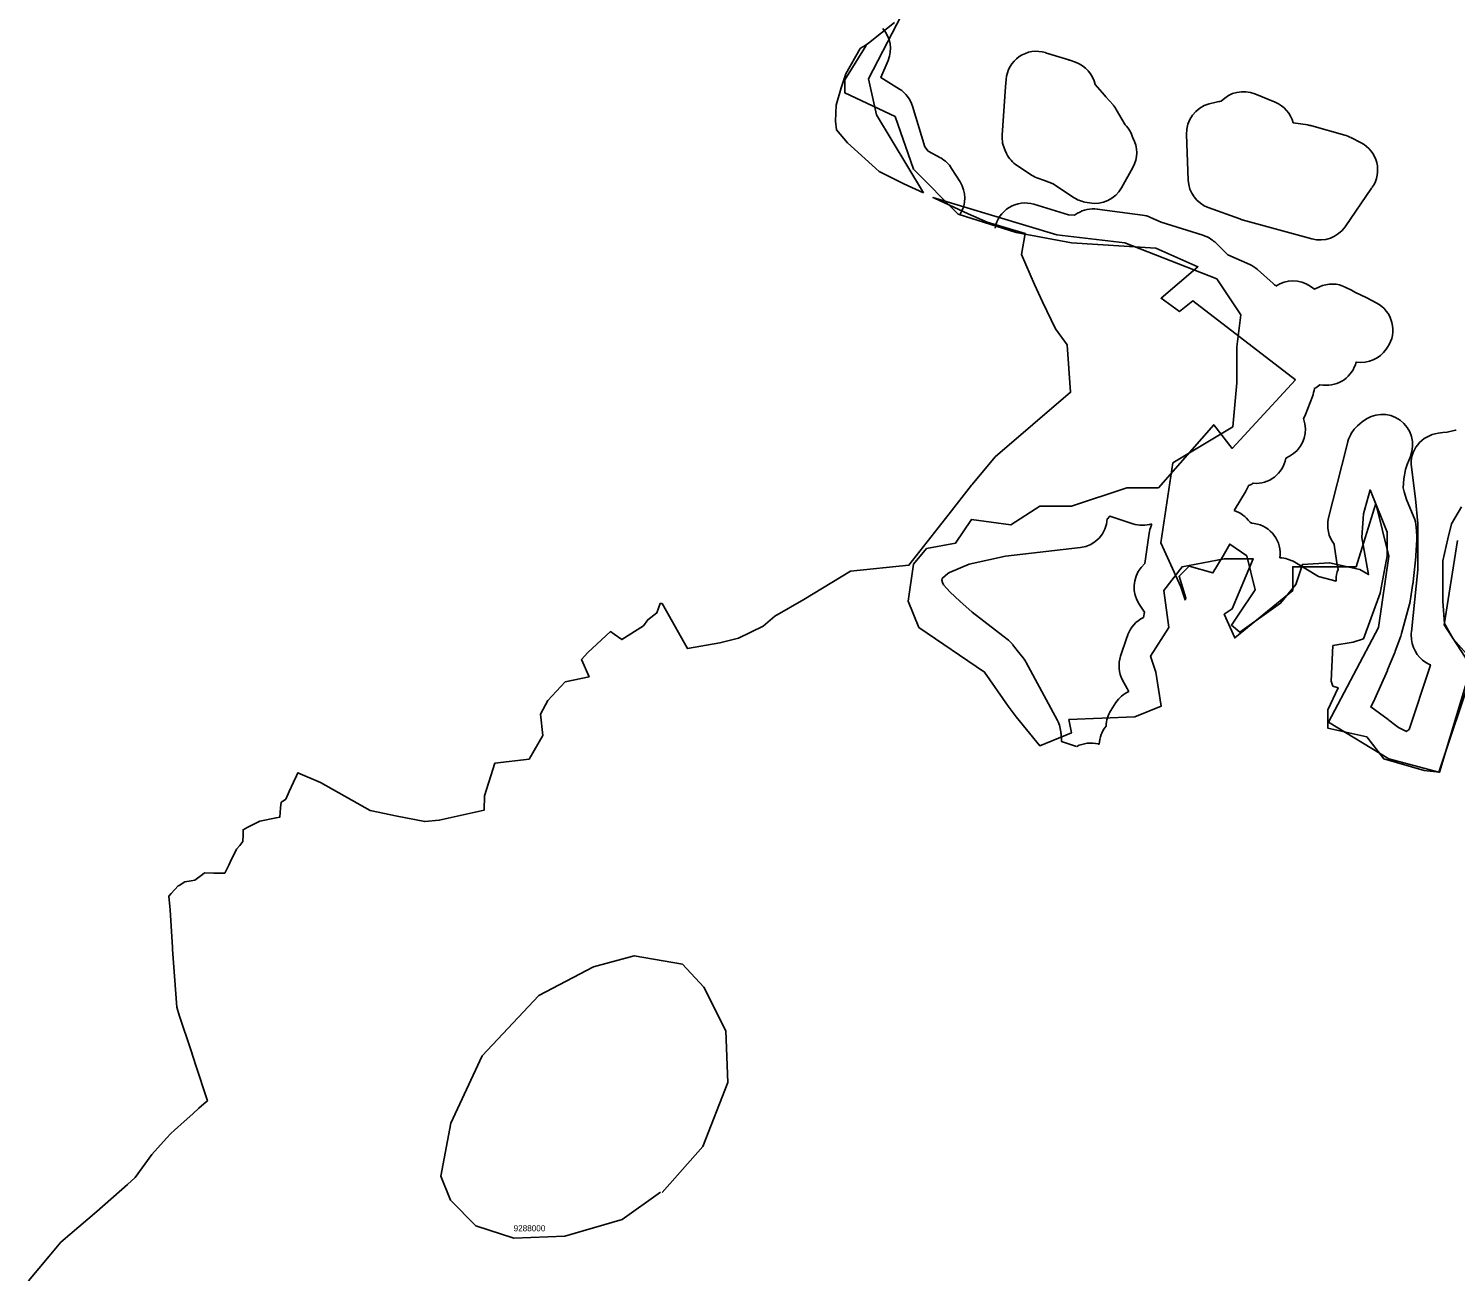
# Model space of a CAD drawing. Extents: x -546762 to -536351, y -1046851 to -1035695.
# Drawn here: x -546557 to -544214, y -1044099 to -1042054 of the extents above; entities that cross this region are included whole.
import ezdxf

# ---------------------------------------------------------------- set-up
doc = ezdxf.new("R2010")
doc.units = 0
for name, color, linetype in [('Vrstva 23', 7, 'Continuous'), ('Vrstva 24', 7, 'Continuous'), ('Vrstva 25', 7, 'Continuous'), ('Vrstva 43', 7, 'Continuous')]:
    doc.layers.add(name, color=color, linetype=linetype)

msp = doc.modelspace()

# ---------------------------------------------------------------- linework, layer by layer
at = {"layer": 'Vrstva 23'}
for points in [[(-544849.2, -1042105.3), (-544887.3, -1042093.6)], [(-544837.8, -1042109.3), (-544847.3, -1042106)], [(-545127.1, -1042153.4), (-545157.4, -1042134.6), (-545145.6, -1042106.3)], [(-544952.8, -1042149.8), (-544958.4, -1042229.1)], [(-544951.9, -1042137.8), (-544952.8, -1042149.7)], [(-544788, -1042166.1), (-544790.3, -1042163.5), (-544805.6, -1042145.9)], [(-544776.4, -1042179.4), (-544788, -1042166.1)], [(-544606.9, -1042174.8), (-544618.3, -1042177.7)], [(-544510.2, -1042175.1), (-544543.6, -1042161.4)], [(-545059.4, -1042266.5), (-545079.7, -1042255.2), (-545085.6, -1042248.3), (-545105.6, -1042181.6)], [(-544756.2, -1042212.2), (-544771, -1042186.9)], [(-544456.6, -1042212.4), (-544480.6, -1042208.9)], [(-544395.8, -1042229), (-544450.2, -1042213.7)], [(-544655.8, -1042228.1), (-544652.9, -1042303)], [(-544368.8, -1042241.8), (-544386.2, -1042232.8)], [(-544953.4, -1042254.5), (-544951.1, -1042259.3)], [(-545027.3, -1042305.9), (-545041.4, -1042283.6)], [(-544933.8, -1042279.1), (-544911.7, -1042293.7)], [(-544762.3, -1042315.5), (-544743.7, -1042282.3)], [(-544901.4, -1042299), (-544888.8, -1042303.6), (-544874.9, -1042308.8), (-544841.2, -1042331.3)], [(-544395.4, -1042379.6), (-544351.9, -1042316.4)], [(-544351.9, -1042316.3), (-544350.6, -1042314.5)], [(-544822.5, -1042339), (-544815.1, -1042340.3)], [(-544834.9, -1042357.4), (-544839.6, -1042360.3), (-544849.6, -1042359.9), (-544906.2, -1042342.7)], [(-544728.2, -1042360.5), (-544802.2, -1042350.5)], [(-544619.9, -1042348.1), (-544568.1, -1042366.8)], [(-544628.7, -1042393.5), (-544697.2, -1042371.8), (-544715, -1042364.1)], [(-544564.4, -1042368), (-544449.9, -1042399.5)], [(-544613.2, -1042401.6), (-544615.6, -1042399.9)], [(-544552, -1042441.6), (-544587.9, -1042425.7), (-544606, -1042407.5)], [(-544513.4, -1042472.8), (-544539.1, -1042449.9)], [(-544437.5, -1042478.2), (-544445.5, -1042481.9), (-544452.7, -1042476.9)], [(-544379.2, -1042486.8), (-544384.8, -1042483.9), (-544394, -1042479.2)], [(-544344.1, -1042504.7), (-544359.9, -1042496.6), (-544379.1, -1042486.8)], [(-544327.8, -1042580.6), (-544325.6, -1042577.5)], [(-544377.2, -1042601.7), (-544376.4, -1042601.8)], [(-544436.6, -1042639), (-544431.4, -1042639.6)], [(-544460.4, -1042688), (-544449, -1042658.5)], [(-544461.5, -1042703.4), (-544462.4, -1042698.9)], [(-544367.1, -1042700), (-544374.9, -1042706.8)], [(-544214.1, -1042713.9), (-544228, -1042717), (-544234.7, -1042717.8), (-544242.8, -1042718.8)], [(-544390.7, -1042732.4), (-544393.5, -1042743.7), (-544422.4, -1042858)], [(-544492.7, -1042759.9), (-544486.7, -1042756.6)], [(-544282.5, -1042856.7), (-544294.7, -1042827.7), (-544298.6, -1042815.2), (-544300, -1042808.6), (-544298.9, -1042793.6), (-544296.4, -1042778.3), (-544293.7, -1042770.2), (-544288.2, -1042757)], [(-544286.4, -1042774.6), (-544280, -1042826.3), (-544276, -1042866.9), (-544275.9, -1042942.9), (-544286.5, -1043044.8)], [(-544554.6, -1042806.2), (-544554.5, -1042805.7)], [(-544553.7, -1042804.8), (-544550.7, -1042803.3)], [(-544577.4, -1042845.8), (-544566.4, -1042827.6), (-544558.9, -1042815.1)], [(-544785.7, -1042859.3), (-544781.8, -1042855), (-544743.7, -1042867.5)], [(-544712.7, -1042867.6), (-544713, -1042868.5)], [(-544544.4, -1042866.9), (-544548.4, -1042866.3), (-544551.9, -1042864.6)], [(-544277.6, -1042887.7), (-544278.7, -1042872.7)], [(-544717, -1042882.9), (-544724.2, -1042932.6)], [(-544413.3, -1042901), (-544412.6, -1042905.9), (-544408.5, -1042935)], [(-544279, -1042919.4), (-544277.6, -1042893.9)], [(-544950.2, -1043057), (-545007.8, -1043012.5), (-545027.9, -1042994.5), (-545027.9, -1042994.5), (-545043.9, -1042980), (-545054.8, -1042967.6), (-545056.3, -1042964.1), (-545057.2, -1042959.9), (-545056.9, -1042957.6), (-545056.4, -1042956.6), (-545047.7, -1042949.3), (-545044.7, -1042947.6), (-545012.6, -1042933.8), (-544952.8, -1042920.9), (-544829.9, -1042906.5)], [(-544283.7, -1042963.1), (-544279.2, -1042922)], [(-544724.3, -1042932.7), (-544730, -1042939.5)], [(-544410.1, -1042959.8), (-544410.1, -1042961.6), (-544439.1, -1042954.1), (-544478.1, -1042930.7)], [(-544407.5, -1042939.8), (-544406.9, -1042942.4)], [(-544288.5, -1042994.4), (-544284, -1042965.6)], [(-544733.5, -1042999.8), (-544724.7, -1043012.9), (-544726.3, -1043021.5)], [(-544302.7, -1043048), (-544289.6, -1042999.6)], [(-544935.2, -1043073.6), (-544941.6, -1043065.6)], [(-544752.3, -1043050.7), (-544753.5, -1043054.1), (-544763.9, -1043084.9)], [(-544313, -1043077), (-544304, -1043052.1)], [(-544286.6, -1043054.7), (-544286.3, -1043057.6)], [(-544923.8, -1043088), (-544933.7, -1043075.5), (-544935.2, -1043073.7)], [(-544325.5, -1043107.4), (-544313.8, -1043079)], [(-544867.7, -1043190.5), (-544919, -1043095.3)], [(-544346.5, -1043155.2), (-544326, -1043108.5)], [(-544256.7, -1043098.6), (-544255.2, -1043099.2), (-544256.9, -1043104.5), (-544290, -1043205.4)], [(-544760.6, -1043124.4), (-544753.3, -1043138.1)], [(-544324.7, -1043188.9), (-544353.1, -1043168.3), (-544347.8, -1043157.8)], [(-544771.5, -1043161.2), (-544779.8, -1043174.1)], [(-544311.9, -1043198.8), (-544323.3, -1043189.9)], [(-544294.8, -1043208.5), (-544307.5, -1043202.3), (-544311.9, -1043198.9)], [(-544836.1, -1043233.3), (-544861.2, -1043225.1), (-544861.8, -1043212)], [(-544799.1, -1043229.7), (-544800.7, -1043229.3)]]:
    msp.add_lwpolyline(points, dxfattribs=at)
for centre, start, end in [((-545191.8, -1042087), 337.3847, 41.2924), ((-544902, -1042141.3), 72.8296, 175.9314), ((-544864, -1042153.1), 70.5568, 72.8296), ((-544854.5, -1042156.5), 12.1909, 70.5568), ((-544902.9, -1042153.3), 175.9314, 175.9544), ((-545153.5, -1042195.9), 16.6863, 58.1684), ((-544825.8, -1042198.9), 41.0272, 41.0307), ((-544594.3, -1042223.2), 95.0827, 104.4945), ((-544562.4, -1042207.7), 67.8064, 136.6015), ((-544529, -1042221.3), 14.3739, 67.8064), ((-544814.2, -1042212.2), 30.3979, 41.0272), ((-544605.8, -1042226.1), 104.4945, 182.2014), ((-544791.8, -1042247.4), 16.13, 44.6377), ((-544463.7, -1042261.9), 74.3371, 81.817), ((-544908.5, -1042232.6), 175.9544, 205.9892), ((-544787.4, -1042257.9), 330.8125, 29.2104), ((-544409.3, -1042277.2), 62.5847, 74.3371), ((-544391.9, -1042286.2), 325.5309, 62.5847), ((-545083.7, -1042310.2), 32.1113, 60.8519), ((-544906.2, -1042237.4), 205.9892, 236.4478), ((-545069.7, -1042332.5), 328.4125, 32.1113), ((-544884.1, -1042252.1), 236.4478, 249.754), ((-544806, -1042291.2), 259.5113, 330.8125), ((-544602.9, -1042301), 182.2014, 250.1209), ((-544393.1, -1042288), 325.4753, 325.5309), ((-544813.4, -1042289.8), 236.1491, 259.5113), ((-544920.8, -1042390.5), 73.0372, 169.9655), ((-544808.8, -1042400.1), 82.3181, 121.4759), ((-544734.8, -1042410), 66.6368, 82.3181), ((-544551.1, -1042319.8), 250.1209, 254.6353), ((-544436.6, -1042351.2), 254.6353, 325.4753), ((-544643.8, -1042441.2), 55.6619, 72.4253), ((-544641.4, -1042442.9), 45, 55.6619), ((-544572.3, -1042487.3), 48.3485, 66.0771), ((-544546.6, -1042510.1), 41.6595, 48.3485), ((-544481, -1042518.2), 55.5487, 124.3809), ((-544416.8, -1042523.7), 62.8883, 114.5216), ((-544401.9, -1042531.3), 62.8902, 62.9511), ((-544366.9, -1042549.2), 325.5932, 62.8998), ((-544369, -1042552.3), 261.5678, 325.5932), ((-544425.8, -1042589.9), 263.5051, 346.4252), ((-544469.3, -1042601.2), 297.9425, 310.8958), ((-544495.6, -1042640.4), 338.8208, 354.2598), ((-544507.1, -1042669.9), 330.7642, 338.8208), ((-544334.4, -1042737.8), 337.5285, 130.8724), ((-544510.6, -1042712.7), 298.6405, 10.6575), ((-544511.5, -1042708.1), 10.6575, 16.0094), ((-544342.2, -1042744.6), 130.8724, 165.8569), ((-544190.6, -1042758), 116.62, 118.0582), ((-544236.8, -1042768.5), 96.8986, 187.0374), ((-544542, -1042751.1), 265.1649, 349.9198), ((-544601.7, -1042789.3), 328.9352, 340.2532), ((-544593.7, -1042774.7), 321.6944, 323.0556), ((-544571.8, -1042758), 295.057, 300.858), ((-544592.7, -1042893.4), 35.2337, 72.1535), ((-544835.7, -1042856.8), 276.6671, 357.2254), ((-544728.1, -1042820), 251.795, 287.8676), ((-544667.5, -1042890.2), 157.5718, 171.668), ((-544665.1, -1042882.8), 163.3626, 166.4481), ((-544551.9, -1042916.3), 351.7201, 81.3696), ((-544373.9, -1042870.2), 165.8317, 218.055), ((-544328.6, -1042876.1), 3.9255, 22.8493), ((-544327.5, -1042891.1), 356.8351, 3.9255), ((-544503.8, -1042973.5), 58.956, 88.3625), ((-544328.9, -1042916.6), 353.8265, 356.8351), ((-544692, -1042971.9), 139.5152, 213.8546), ((-544674.8, -1042939.8), 171.668, 171.8853), ((-544360.1, -1042960.1), 159.3153, 179.7451), ((-544358.9, -1042928), 188.0694, 193.6986), ((-544333.4, -1042957.8), 351.0315, 353.8265), ((-544337.9, -1042986.6), 344.9633, 351.0315), ((-544705, -1043066.7), 115.2522, 161.3619), ((-544980.8, -1043096.6), 38.3985, 52.3), ((-544350.9, -1043035), 339.9929, 344.9633), ((-544236.8, -1043050), 174.0675, 185.4499), ((-544236.5, -1043052.8), 185.4499, 246.1491), ((-544974.4, -1043104.7), 38.329, 38.3985), ((-544963, -1043119), 28.3051, 38.4181), ((-544716.5, -1043100.9), 161.359, 208.0161), ((-544360, -1043059.9), 337.5854, 339.9929), ((-544371.7, -1043088.3), 336.2394, 337.5854), ((-544729.5, -1043188.4), 114.6868, 147.139), ((-544709.2, -1043114.6), 208.0161, 214.5271), ((-544392.3, -1043135), 332.8265, 336.2394), ((-544737.8, -1043201.3), 147.139, 178.418), ((-544911.8, -1043214.2), 2.5506, 28.3051), ((-544749.1, -1043231.6), 140.6981, 177.8378), ((-544354, -1043229.4), 52.1666, 54.0551), ((-544342.6, -1043238.3), 52.125, 52.1666), ((-544265.8, -1043249.2), 119.0206, 125.5078), ((-544813, -1043277.7), 75.6926, 117.4409)]:
    msp.add_arc(centre, 50, start, end, dxfattribs=at)
at = {"layer": 'Vrstva 24'}
for points in [[(-545087.6, -1042324.1), (-545164.5, -1042195.8), (-545177.7, -1042136.7), (-545046, -1041881.4)], [(-545135.4, -1042044.2), (-545178, -1042078.1), (-545185.2, -1042082.8), (-545188, -1042084.6), (-545191.8, -1042087), (-545215.3, -1042128.1), (-545222.9, -1042151.6), (-545231, -1042179.8), (-545232.1, -1042206), (-545230.4, -1042220.5), (-545212.6, -1042241.9), (-545160.2, -1042288.8), (-545119.6, -1042309), (-545087.6, -1042324.1)], [(-544187.6, -1043100.8), (-544240.4, -1043275.7), (-544265.3, -1043273), (-544332, -1043253.5), (-544359.8, -1043217.4), (-544423.6, -1043203.5), (-544423.6, -1043173), (-544407, -1043136.9), (-544415.3, -1043134.1), (-544418.1, -1043125.8), (-544415.3, -1043067.5), (-544382, -1043061.9), (-544365.3, -1043056.4), (-544337.5, -1042981.4), (-544326.4, -1042920.3), (-544326.4, -1042881.4), (-544354.2, -1042812), (-544365.3, -1042850.9), (-544368.1, -1042889.8), (-544357, -1042950.9), (-544370.9, -1042942.5), (-544420.8, -1042931.4), (-544465.3, -1042934.2), (-544476.4, -1042967.5), (-544501.4, -1042998.1), (-544568, -1043045.3), (-544581.9, -1043034.2), (-544570.8, -1043017.5), (-544543, -1042975.8), (-544556.9, -1042920.3), (-544584.7, -1042900.9), (-544595.8, -1042920.3), (-544612.4, -1042948.1), (-544651.3, -1042937), (-544668, -1042953.6), (-544656.9, -1042989.7), (-544658.2, -1042992.5), (-544665.1, -1042971.2), (-544698, -1042898.9), (-544678.3, -1042767.5), (-544579.7, -1042708.4), (-544573.1, -1042636.1), (-544573.1, -1042576.9), (-544566.6, -1042524.4), (-544606, -1042465.2), (-544757.1, -1042406.1), (-544868.8, -1042393), (-545072.2, -1042331.3), (-545069.7, -1042332.5), (-545014.3, -1042358.6), (-544982.9, -1042371.9), (-544920.8, -1042390.5), (-544926.7, -1042425.2), (-544905.4, -1042474.4), (-544892.1, -1042503.1), (-544870.7, -1042547.5), (-544851.6, -1042573.6), (-544846.2, -1042651.4), (-544969.8, -1042757.8), (-545007.9, -1042802.9), (-545008.9, -1042804.2), (-545045.5, -1042851.4), (-545111.6, -1042935.6), (-545207.4, -1042945.5), (-545283.9, -1042991.7), (-545331.4, -1043019.4), (-545351, -1043035.5), (-545391.5, -1043055.5), (-545421.7, -1043063.3), (-545474.9, -1043072.5), (-545516.8, -1042998.5), (-545520.1, -1042998.2), (-545525.5, -1043013.9), (-545540.2, -1043025.1), (-545547.3, -1043035.2), (-545583, -1043057.7), (-545595.4, -1043048.9), (-545601.3, -1043044.7), (-545638.9, -1043078.9), (-545648.9, -1043090.6), (-545636.6, -1043118.8), (-545675.7, -1043127.3), (-545704.5, -1043157.8), (-545716.5, -1043180.5), (-545712.8, -1043215.3), (-545735.2, -1043254.4), (-545791.2, -1043260.8), (-545808.2, -1043314.3), (-545809, -1043338), (-545882.6, -1043354.5), (-545906.3, -1043356.7), (-545951.7, -1043348), (-545996.1, -1043338.3), (-546077.4, -1043292.3), (-546114.8, -1043276.4), (-546117.2, -1043281.6), (-546121.9, -1043292.1), (-546128.8, -1043307.4), (-546134.4, -1043319.8), (-546136.7, -1043321.4), (-546142.4, -1043325.1), (-546143.1, -1043334.1), (-546144.2, -1043349.3), (-546150.4, -1043350.5), (-546177, -1043355.8), (-546182.6, -1043358.7), (-546197, -1043366.1), (-546204.6, -1043370.1), (-546204.8, -1043378.1), (-546205, -1043389.6), (-546210.1, -1043395.8), (-546215.3, -1043402.2), (-546217.6, -1043406.8), (-546224, -1043419.7), (-546228.3, -1043428.4), (-546234.8, -1043441.3), (-546240.6, -1043441.3), (-546252.7, -1043441.3), (-546268.1, -1043441.2), (-546271.3, -1043443.6), (-546283.9, -1043452.8), (-546289.8, -1043453.9), (-546300.3, -1043455.9), (-546309.9, -1043461.8), (-546311.1, -1043462.5), (-546322.7, -1043475), (-546326.7, -1043479.4), (-546324.8, -1043496.2), (-546324.2, -1043501.9), (-546320.7, -1043563.6), (-546320.4, -1043567), (-546313.7, -1043661.8), (-546309.5, -1043674.5), (-546290, -1043733.6), (-546282.7, -1043755.9), (-546263.3, -1043815.3), (-546268.9, -1043820.3), (-546277.1, -1043827.7), (-546287.4, -1043836.8), (-546301.7, -1043849.7), (-546317.2, -1043863.4), (-546323.4, -1043869), (-546330.4, -1043876.8), (-546354.5, -1043903.5), (-546381.7, -1043941.5), (-546394.7, -1043952.9), (-546444.7, -1043997.1), (-546504.1, -1044047.7), (-546523.1, -1044070.5), (-546557, -1044111.2)], [(-544204.3, -1042839.8), (-544220.9, -1042867.6), (-544226.5, -1042892.5), (-544234.8, -1042928.6), (-544234.8, -1042995.3), (-544232, -1043031.4), (-544218.1, -1043056.4), (-544195.9, -1043081.4)]]:
    msp.add_lwpolyline(points, dxfattribs=at)
at = {"layer": 'Vrstva 25'}
msp.add_lwpolyline([(-544210.9, -1042894.9), (-544232.6, -1043033.4), (-544184.9, -1043106.9), (-544241.2, -1043275.6), (-544323.4, -1043253.9), (-544422.8, -1043193.4), (-544340.7, -1043037.7), (-544323.4, -1042920.9), (-544345, -1042834.4), (-544377.4, -1042938.2), (-544481.3, -1042938.2), (-544481.3, -1042977.1), (-544576.4, -1043055), (-544593.7, -1043016.1), (-544580.7, -1043007.4), (-544546.1, -1042925.3), (-544593.7, -1042925.3), (-544662.9, -1042938.2), (-544693.1, -1042977.1), (-544684.5, -1043037.7), (-544714.8, -1043085.2), (-544706.1, -1043111.2), (-544697.5, -1043167.4), (-544740.8, -1043184.8), (-544848.9, -1043189.1), (-544844.5, -1043210.7), (-544896.4, -1043232.3), (-544935.4, -1043184.8), (-544948.3, -1043167.4), (-544987.3, -1043111.2), (-545095.4, -1043037.7), (-545112.7, -1042994.4), (-545104, -1042933.9), (-545082.4, -1042907.9), (-545034.8, -1042899.3), (-545008.9, -1042860.4), (-544944, -1042869), (-544896.4, -1042838.7), (-544844.5, -1042838.7), (-544753.7, -1042808.4), (-544701.8, -1042808.4), (-544611, -1042704.7), (-544580.7, -1042743.6), (-544476.9, -1042631.1), (-544645.6, -1042501.4), (-544667.2, -1042518.7), (-544697.5, -1042497.1), (-544636.9, -1042445.2), (-544706.1, -1042414.9), (-544844.5, -1042406.2), (-544935.4, -1042388.9), (-545030.5, -1042358.7), (-545104, -1042285.1), (-545134.3, -1042198.6), (-545216.5, -1042159.7), (-545216.5, -1042138.1), (-545181.9, -1042081.9)], dxfattribs=at)
at = {"layer": 'Vrstva 43'}
msp.add_lwpolyline([(-545519.2, -1043965.6), (-545582.3, -1044010.5), (-545676.5, -1044037.9), (-545760.2, -1044040.9), (-545822.5, -1044021.1), (-545864.3, -1043978.6), (-545880.3, -1043939), (-545863.6, -1043852.3), (-545811.9, -1043741.3), (-545719.1, -1043642.5), (-545629.4, -1043595.4), (-545562.5, -1043577.1), (-545483.4, -1043590.8), (-545448.4, -1043628.8), (-545412, -1043700.3), (-545408.9, -1043785.4), (-545450, -1043890.4), (-545516.4, -1043966)], dxfattribs=at)

# ---------------------------------------------------------------- texts
msp.add_text('9288000', height=10, dxfattribs=at).set_placement((-545760.5, -1044029.8))

doc.saveas('drawing.dxf')
